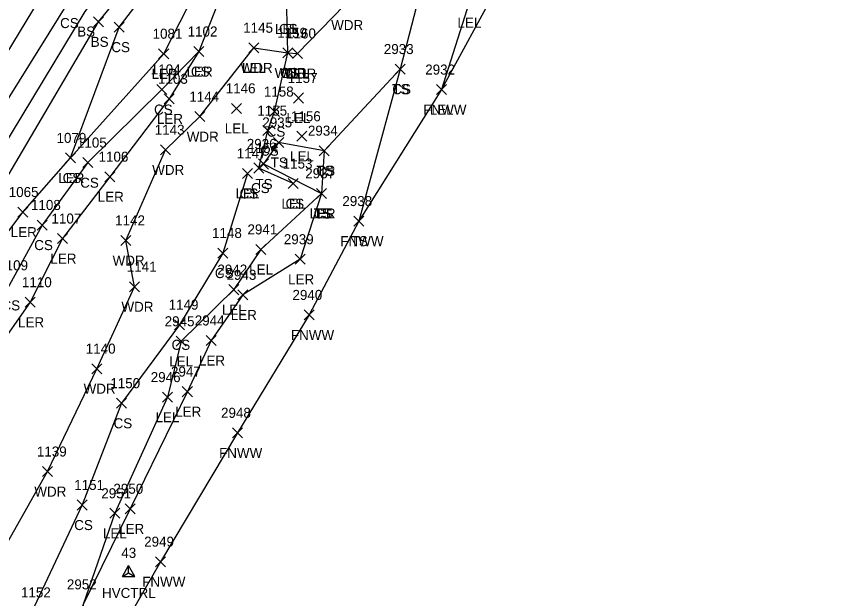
# Model space of a CAD drawing. Extents: x 1483143 to 1488182, y 802902 to 807581.
# Drawn here: x 1487188.6 to 1487354.4, y 804993.1 to 805109.1 of the extents above; entities that cross this region are included whole.
import ezdxf

# ---------------------------------------------------------------- set-up
doc = ezdxf.new("R2010")
doc.units = 0
for name, color, linetype in [('C_A', 7, 'Continuous'), ('C_I', 7, 'Continuous'), ('CPSM', 7, 'Continuous'), ('L_A', 7, 'Continuous'), ('L_I', 7, 'Continuous'), ('L_TIC', 7, 'Continuous'), ('LARO', 7, 'Continuous'), ('LAWA', 7, 'Continuous'), ('LELB', 7, 'Continuous'), ('LFNC', 7, 'Continuous')]:
    doc.layers.add(name, color=color, linetype=linetype)

msp = doc.modelspace()

# ---------------------------------------------------------------- linework, layer by layer
at = {"layer": 'CPSM'}
for p, q in [((1487209.65, 804997.5), (1487210.9, 804999.66)), ((1487212.15, 804997.5), (1487210.9, 804999.66)), ((1487210.9, 804998.22), (1487210.9, 804999.66)), ((1487209.65, 804997.5), (1487210.9, 804998.22)), ((1487209.65, 804997.5), (1487212.15, 804997.5)), ((1487210.9, 804998.22), (1487210.9, 804998.22)), ((1487210.9, 804998.22), (1487212.15, 804997.5))]:
    msp.add_line(p, q, dxfattribs=at)
at = {"layer": 'L_TIC'}
for points in [[(1487203.9, 805107.12), (1487205.9, 805109.12)], [(1487205.9, 805107.12), (1487203.9, 805109.12)], [(1487208.02, 805106.06), (1487210.02, 805108.06)], [(1487210.02, 805106.06), (1487208.02, 805108.06)], [(1487223.88, 805101.18), (1487225.88, 805103.18)], [(1487225.88, 805101.18), (1487223.88, 805103.18)], [(1487223.88, 805101.18), (1487225.88, 805103.18)], [(1487225.88, 805101.18), (1487223.88, 805103.18)], [(1487234.87, 805101.93), (1487236.87, 805103.93)], [(1487236.87, 805101.93), (1487234.87, 805103.93)], [(1487234.87, 805101.93), (1487236.87, 805103.93)], [(1487236.87, 805101.93), (1487234.87, 805103.93)], [(1487216.89, 805100.74), (1487218.89, 805102.74)], [(1487218.89, 805100.74), (1487216.89, 805102.74)], [(1487241.66, 805100.92), (1487243.66, 805102.92)], [(1487243.66, 805100.92), (1487241.66, 805102.92)], [(1487241.66, 805100.92), (1487243.66, 805102.92)], [(1487243.66, 805100.92), (1487241.66, 805102.92)], [(1487243.56, 805100.79), (1487245.56, 805102.79)], [(1487245.56, 805100.79), (1487243.56, 805102.79)], [(1487243.56, 805100.79), (1487245.56, 805102.79)], [(1487245.56, 805100.79), (1487243.56, 805102.79)], [(1487264.05, 805097.68), (1487266.05, 805099.68)], [(1487266.05, 805097.68), (1487264.05, 805099.68)], [(1487264.05, 805097.68), (1487266.05, 805099.68)], [(1487266.05, 805097.68), (1487264.05, 805099.68)], [(1487216.52, 805093.61), (1487218.52, 805095.61)], [(1487218.52, 805093.61), (1487216.52, 805095.61)], [(1487272.31, 805093.59), (1487274.31, 805095.59)], [(1487274.31, 805093.59), (1487272.31, 805095.59)], [(1487272.31, 805093.59), (1487274.31, 805095.59)], [(1487274.31, 805093.59), (1487272.31, 805095.59)], [(1487217.96, 805091.75), (1487219.96, 805093.75)], [(1487219.96, 805091.75), (1487217.96, 805093.75)], [(1487243.75, 805091.92), (1487245.75, 805093.92)], [(1487245.75, 805091.92), (1487243.75, 805093.92)], [(1487231.44, 805089.85), (1487233.44, 805091.85)], [(1487233.44, 805089.85), (1487231.44, 805091.85)], [(1487224.12, 805088.2), (1487226.12, 805090.2)], [(1487226.12, 805088.2), (1487224.12, 805090.2)], [(1487238.99, 805089.2), (1487240.99, 805091.2)], [(1487240.99, 805089.2), (1487238.99, 805091.2)], [(1487237.69, 805085.41), (1487239.69, 805087.41)], [(1487239.69, 805085.41), (1487237.69, 805087.41)], [(1487239.82, 805083.06), (1487241.82, 805085.06)], [(1487241.82, 805083.06), (1487239.82, 805085.06)], [(1487244.45, 805084.28), (1487246.45, 805086.28)], [(1487246.45, 805084.28), (1487244.45, 805086.28)], [(1487217.24, 805081.58), (1487219.24, 805083.58)], [(1487219.24, 805081.58), (1487217.24, 805083.58)], [(1487248.91, 805081.41), (1487250.91, 805083.41)], [(1487250.91, 805081.41), (1487248.91, 805083.41)], [(1487248.91, 805081.41), (1487250.91, 805083.41)], [(1487250.91, 805081.41), (1487248.91, 805083.41)], [(1487198.3, 805079.96), (1487200.3, 805081.96)], [(1487200.3, 805079.96), (1487198.3, 805081.96)], [(1487198.3, 805079.96), (1487200.3, 805081.96)], [(1487200.3, 805079.96), (1487198.3, 805081.96)], [(1487201.79, 805079.03), (1487203.79, 805081.03)], [(1487203.79, 805079.03), (1487201.79, 805081.03)], [(1487235.87, 805077.96), (1487237.87, 805079.96)], [(1487237.87, 805077.96), (1487235.87, 805079.96)], [(1487236.78, 805078.76), (1487238.78, 805080.76)], [(1487238.78, 805078.76), (1487236.78, 805080.76)], [(1487206.16, 805076.22), (1487208.16, 805078.22)], [(1487208.16, 805076.22), (1487206.16, 805078.22)], [(1487233.59, 805076.88), (1487235.59, 805078.88)], [(1487235.59, 805076.88), (1487233.59, 805078.88)], [(1487233.59, 805076.88), (1487235.59, 805078.88)], [(1487235.59, 805076.88), (1487233.59, 805078.88)], [(1487242.74, 805074.84), (1487244.74, 805076.84)], [(1487244.74, 805074.84), (1487242.74, 805076.84)], [(1487242.74, 805074.84), (1487244.74, 805076.84)], [(1487244.74, 805074.84), (1487242.74, 805076.84)], [(1487248.38, 805072.9), (1487250.38, 805074.9)], [(1487250.38, 805072.9), (1487248.38, 805074.9)], [(1487248.38, 805072.9), (1487250.38, 805074.9)], [(1487250.38, 805072.9), (1487248.38, 805074.9)], [(1487248.38, 805072.9), (1487250.38, 805074.9)], [(1487250.38, 805072.9), (1487248.38, 805074.9)], [(1487248.38, 805072.9), (1487250.38, 805074.9)], [(1487250.38, 805072.9), (1487248.38, 805074.9)], [(1487188.8, 805069.17), (1487190.8, 805071.17)], [(1487190.8, 805069.17), (1487188.8, 805071.17)], [(1487192.63, 805066.59), (1487194.63, 805068.59)], [(1487194.63, 805066.59), (1487192.63, 805068.59)], [(1487255.78, 805067.37), (1487257.78, 805069.37)], [(1487257.78, 805067.37), (1487255.78, 805069.37)], [(1487255.78, 805067.37), (1487257.78, 805069.37)], [(1487257.78, 805067.37), (1487255.78, 805069.37)], [(1487196.72, 805063.88), (1487198.72, 805065.88)], [(1487198.72, 805063.88), (1487196.72, 805065.88)], [(1487209.34, 805063.51), (1487211.34, 805065.51)], [(1487211.34, 805063.51), (1487209.34, 805065.51)], [(1487236.29, 805061.72), (1487238.29, 805063.72)], [(1487238.29, 805061.72), (1487236.29, 805063.72)], [(1487228.66, 805061), (1487230.66, 805063)], [(1487230.66, 805061), (1487228.66, 805063)], [(1487244.12, 805059.76), (1487246.12, 805061.76)], [(1487246.12, 805059.76), (1487244.12, 805061.76)], [(1487211.1, 805054.28), (1487213.1, 805056.28)], [(1487213.1, 805054.28), (1487211.1, 805056.28)], [(1487230.86, 805053.7), (1487232.86, 805055.7)], [(1487232.86, 805053.7), (1487230.86, 805055.7)], [(1487232.68, 805052.66), (1487234.68, 805054.66)], [(1487234.68, 805052.66), (1487232.68, 805054.66)], [(1487190.27, 805051.19), (1487192.27, 805053.19)], [(1487192.27, 805051.19), (1487190.27, 805053.19)], [(1487245.92, 805048.65), (1487247.92, 805050.65)], [(1487247.92, 805048.65), (1487245.92, 805050.65)], [(1487220.02, 805046.7), (1487222.02, 805048.7)], [(1487222.02, 805046.7), (1487220.02, 805048.7)], [(1487220.35, 805043.4), (1487222.35, 805045.4)], [(1487222.35, 805043.4), (1487220.35, 805045.4)], [(1487226.35, 805043.56), (1487228.35, 805045.56)], [(1487228.35, 805043.56), (1487226.35, 805045.56)], [(1487203.56, 805037.94), (1487205.56, 805039.94)], [(1487205.56, 805037.94), (1487203.56, 805039.94)], [(1487221.61, 805033.36), (1487223.61, 805035.36)], [(1487223.61, 805033.36), (1487221.61, 805035.36)], [(1487217.63, 805032.26), (1487219.63, 805034.26)], [(1487219.63, 805032.26), (1487217.63, 805034.26)], [(1487208.46, 805031.05), (1487210.46, 805033.05)], [(1487210.46, 805031.05), (1487208.46, 805033.05)], [(1487231.59, 805025.14), (1487233.59, 805027.14)], [(1487233.59, 805025.14), (1487231.59, 805027.14)], [(1487193.73, 805017.42), (1487195.73, 805019.42)], [(1487195.73, 805017.42), (1487193.73, 805019.42)], [(1487200.61, 805010.76), (1487202.61, 805012.76)], [(1487202.61, 805010.76), (1487200.61, 805012.76)], [(1487210.22, 805010), (1487212.22, 805012)], [(1487212.22, 805010), (1487210.22, 805012)], [(1487207.14, 805009.1), (1487209.14, 805011.1)], [(1487209.14, 805009.1), (1487207.14, 805011.1)], [(1487216.26, 804999.45), (1487218.26, 805001.45)], [(1487218.26, 804999.45), (1487216.26, 805001.45)]]:
    msp.add_lwpolyline(points, dxfattribs=at)
at = {"layer": 'LARO'}
for points in [[(1487124.31, 804973.13), (1487145.49, 805006.81), (1487169.77, 805044.38), (1487180.59, 805057.87), (1487189.8, 805070.17), (1487199.3, 805080.96), (1487217.89, 805101.74), (1487229.45, 805124.32), (1487246.83, 805150.76), (1487254.41, 805169.19), (1487269.28, 805204.96), (1487282.34, 805212.7), (1487284.63, 805226.5), (1487290.62, 805235.83), (1487297.31, 805243.76), (1487306.73, 805267.09), (1487309.81, 805276.71), (1487327.69, 805305.4), (1487333.49, 805320.05), (1487351.27, 805341.81), (1487376.58, 805390.13), (1487400.9, 805431.24), (1487423.77, 805476.17), (1487448.72, 805522.61)], [(1487294.36, 805131.51), (1487282.19, 805124.75), (1487278.84, 805111.94), (1487273.31, 805094.59)], [(1487224.88, 805102.18), (1487218.96, 805092.75), (1487207.16, 805077.22), (1487197.72, 805064.88), (1487191.27, 805052.19), (1487172.27, 805025.16), (1487162.87, 805006.15), (1487154.72, 804982.09), (1487145.82, 804977.85), (1487136.39, 804963.75), (1487123.38, 804946.04), (1487114.55, 804933.59), (1487107.15, 804926.23), (1487097.47, 804917.18), (1487108.5, 804913.17)], [(1487249.38, 805073.9), (1487237.29, 805062.72), (1487231.86, 805054.7), (1487221.35, 805044.4), (1487218.63, 805033.26), (1487208.14, 805010.1), (1487201.85, 804991.93), (1487196.68, 804979.98), (1487199.24, 804969.27)], [(1487249.38, 805073.9), (1487245.12, 805060.76), (1487233.68, 805053.66), (1487227.35, 805044.56), (1487222.61, 805034.36), (1487211.22, 805011), (1487201.85, 804991.93), (1487203.24, 804976.05)]]:
    msp.add_lwpolyline(points, dxfattribs=at)
at = {"layer": 'LAWA'}
msp.add_lwpolyline([(1487164.31, 804973.06), (1487181.36, 804994.82), (1487194.73, 805018.42), (1487204.56, 805038.94), (1487212.1, 805055.28), (1487210.34, 805064.51), (1487218.24, 805082.58), (1487225.12, 805089.2), (1487235.87, 805102.93), (1487242.66, 805101.92), (1487244.56, 805101.79), (1487253.92, 805111.46), (1487254.69, 805139.81), (1487264.81, 805134.72), (1487277.92, 805155.83), (1487279.64, 805173.04), (1487288.55, 805192.53), (1487294.52, 805206.51)], dxfattribs=at)
at = {"layer": 'LELB'}
for points in [[(1487199.3, 805080.96), (1487209.02, 805107.06), (1487224.53, 805127.21), (1487240.95, 805152.24), (1487249.95, 805171.94), (1487269.65, 805210.5), (1487285.86, 805237.33), (1487303.36, 805267.84), (1487322.25, 805302.17), (1487347.45, 805347.07), (1487376.58, 805390.13), (1487398.58, 805433.78), (1487419.88, 805479.75), (1487445.41, 805524.09), (1487470.45, 805569.86), (1487486.06, 805603.16), (1487492.1, 805615.56), (1487500.68, 805632.42), (1487507.33, 805640.17), (1487520.3, 805671.34), (1487528.77, 805686.31), (1487539.17, 805698.49)], [(1487108.71, 804980.78), (1487132.66, 805016.32), (1487156.92, 805053.98), (1487173.31, 805079.98), (1487194.46, 805114.79), (1487207.05, 805135.95), (1487220.86, 805159.73), (1487233.38, 805181.3), (1487254.33, 805216.27), (1487271.44, 805245.69), (1487289.79, 805275.85), (1487308.89, 805309.94), (1487335.6, 805356.15), (1487359.27, 805398.59), (1487383.94, 805443.57), (1487406.66, 805485.41), (1487431.45, 805531.24)], [(1487141.45, 805012.57), (1487160.97, 805051.58), (1487177.59, 805077.87), (1487198.8, 805111.86), (1487211.59, 805133.5), (1487225.91, 805156.73), (1487238.62, 805176.26), (1487258.28, 805214.16), (1487275.11, 805243.36), (1487293.13, 805273.9), (1487313.26, 805307.35), (1487339.04, 805353.08), (1487362.83, 805397.01), (1487388.55, 805442.86), (1487410.04, 805483.24), (1487436.07, 805529.53)], [(1487115.55, 804977.3), (1487141.45, 805012.57), (1487163.51, 805049.72), (1487181.31, 805075.62), (1487202.21, 805110.17), (1487217.83, 805130.45), (1487232, 805156.36), (1487242.54, 805175.79), (1487260.94, 805211.88), (1487278.65, 805241.13), (1487296.94, 805270.92), (1487316.03, 805304.83), (1487341.87, 805350.7), (1487367.6, 805395.34), (1487392.63, 805437.94), (1487413.83, 805481.53), (1487440.22, 805526.89)], [(1487119.27, 804975.75), (1487145.32, 805010.11), (1487166.09, 805047.54), (1487184.56, 805073.64), (1487204.9, 805108.12), (1487221.47, 805128.3), (1487235.08, 805155.22), (1487247.48, 805170.55), (1487262.97, 805210.14), (1487282.96, 805240.11), (1487299.52, 805269.42), (1487319.05, 805303.47), (1487344.42, 805349.03), (1487372.12, 805390.86), (1487397.58, 805436.46), (1487417, 805480.8), (1487442.28, 805525.8)], [(1487243.74, 805075.84), (1487236.87, 805078.96), (1487238.69, 805086.41), (1487239.99, 805090.2), (1487242.66, 805101.92), (1487242.45, 805110.69), (1487247.2, 805124.73), (1487252.07, 805141.93), (1487257.35, 805153.28), (1487261.02, 805166.68), (1487265.7, 805175.24), (1487270.25, 805187.46), (1487269.03, 805191.93), (1487273.39, 805203.42), (1487279.08, 805203.72)], [(1487246.83, 805150.76), (1487242.89, 805139.86), (1487233.12, 805123.13), (1487224.88, 805102.18), (1487217.52, 805094.61), (1487202.79, 805080.03), (1487193.63, 805067.59), (1487187.1, 805055.56), (1487168.64, 805033.48), (1487158.81, 805020.55), (1487157.67, 805011.55), (1487148.3, 805000.05), (1487147.3, 804990.5), (1487140.47, 804987.56), (1487138.01, 804979.27), (1487134.54, 804971.88), (1487127.64, 804963.81), (1487118.59, 804952.09), (1487110, 804937.1), (1487101.9, 804929.94), (1487094.26, 804919.39), (1487097.47, 804917.18)], [(1487282.19, 805124.75), (1487270.03, 805117.96), (1487265.05, 805098.68), (1487256.78, 805068.37)], [(1487265.05, 805098.68), (1487249.91, 805082.41), (1487249.38, 805073.9)], [(1487249.91, 805082.41), (1487240.82, 805084.06), (1487237.78, 805079.76), (1487249.38, 805073.9)], [(1487234.59, 805077.88), (1487229.66, 805062), (1487221.02, 805047.7), (1487209.46, 805032.05), (1487201.61, 805011.76), (1487191.55, 804990.32)]]:
    msp.add_lwpolyline(points, dxfattribs=at)
at = {"layer": 'LFNC'}
msp.add_lwpolyline([(1487486.09, 805303.62), (1487464.01, 805287.37), (1487426.01, 805259.99), (1487401.42, 805242.52), (1487400.19, 805241.82), (1487381.81, 805228.11), (1487374.75, 805223.04), (1487372.52, 805220.64), (1487362.23, 805213.48), (1487358.33, 805209.86), (1487353.9, 805206.31), (1487340.39, 805197.17), (1487324.4, 805185.57), (1487312.71, 805164.9), (1487301.18, 805144.21), (1487298.04, 805137.83), (1487294.36, 805131.51), (1487284.56, 805115.26), (1487273.31, 805094.59), (1487256.78, 805068.37), (1487246.92, 805049.65), (1487232.59, 805026.14), (1487217.26, 805000.45), (1487203.24, 804976.05)], dxfattribs=at)

# ---------------------------------------------------------------- texts
at = {"layer": 'C_A'}
msp.add_text('HVCTRL', height=2, dxfattribs=at).set_placement((1487205.6, 804993.22))
at = {"layer": 'C_I'}
msp.add_text('43', height=2, dxfattribs=at).set_placement((1487209.44, 805001.22))
at = {"layer": 'L_A'}
for s, p in [('CS', (1487197.24, 805106.86)), ('WDR', (1487251.29, 805106.46)), ('LEL', (1487276.48, 805106.94)), ('BS', (1487200.65, 805105.17)), ('LEL', (1487240.09, 805105.69)), ('CS', (1487240.89, 805105.69)), ('BS', (1487203.34, 805103.12)), ('CS', (1487207.46, 805102.06)), ('WDR', (1487233.23, 805097.93)), ('LEL', (1487233.51, 805097.93)), ('LER', (1487215.47, 805096.74)), ('LER', (1487222.46, 805097.18)), ('CS', (1487223.32, 805097.18)), ('WDR', (1487240.02, 805096.92)), ('CS', (1487241.1, 805096.92)), ('WDR', (1487241.92, 805096.79)), ('LEL', (1487242.2, 805096.79)), ('TS', (1487263.46, 805093.68)), ('CS', (1487263.49, 805093.68)), ('CS', (1487215.97, 805089.61)), ('FNWW', (1487269.66, 805089.59)), ('LEL', (1487270.95, 805089.59)), ('LER', (1487216.54, 805087.75)), ('LEL', (1487242.38, 805087.92)), ('LEL', (1487230.08, 805085.85)), ('CS', (1487238.43, 805085.2)), ('WDR', (1487222.49, 805084.2)), ('CS', (1487237.13, 805081.41)), ('LEL', (1487243.09, 805080.28)), ('TS', (1487239.23, 805079.06)), ('WDR', (1487215.6, 805077.58)), ('TS', (1487248.32, 805077.41)), ('CS', (1487248.35, 805077.41)), ('LER', (1487196.88, 805075.96)), ('CS', (1487197.74, 805075.96)), ('CS', (1487201.24, 805075.03)), ('TS', (1487236.19, 805074.76)), ('LEL', (1487232.23, 805072.88)), ('CS', (1487233.03, 805072.88)), ('CS', (1487235.31, 805073.96)), ('LER', (1487204.74, 805072.22)), ('LEL', (1487241.38, 805070.84)), ('CS', (1487242.19, 805070.84)), ('LER', (1487246.96, 805068.9)), ('LEL', (1487247.01, 805068.9)), ('TS', (1487247.79, 805068.9)), ('CS', (1487247.82, 805068.9)), ('LER', (1487187.39, 805065.17)), ('FNWW', (1487253.13, 805063.37)), ('TS', (1487255.19, 805063.37)), ('CS', (1487192.08, 805062.59)), ('LER', (1487195.3, 805059.88)), ('WDR', (1487207.7, 805059.51)), ('CS', (1487228.1, 805057)), ('LEL', (1487234.93, 805057.72)), ('LER', (1487242.7, 805055.76)), ('CS', (1487185.55, 805050.56)), ('WDR', (1487209.47, 805050.28)), ('LEL', (1487229.5, 805049.7)), ('LER', (1487231.27, 805048.66)), ('LER', (1487188.85, 805047.19)), ('FNWW', (1487243.27, 805044.65)), ('CS', (1487219.46, 805042.7)), ('LEL', (1487218.99, 805039.4)), ('LER', (1487224.93, 805039.56)), ('WDR', (1487201.93, 805033.94)), ('LEL', (1487216.26, 805028.26)), ('LER', (1487220.19, 805029.36)), ('CS', (1487207.9, 805027.05)), ('FNWW', (1487228.94, 805021.14)), ('WDR', (1487192.1, 805013.42)), ('CS', (1487200.05, 805006.76)), ('LEL', (1487205.78, 805005.1)), ('LER', (1487208.8, 805006)), ('FNWW', (1487213.61, 804995.45))]:
    msp.add_text(s, height=2, dxfattribs=at).set_placement(p)
at = {"layer": 'L_I'}
for s, p in [('1081', (1487215.68, 805104.74)), ('1102', (1487222.67, 805105.18)), ('1102', (1487222.67, 805105.18)), ('1145', (1487233.74, 805105.93)), ('1145', (1487233.74, 805105.93)), ('1159', (1487240.52, 805104.92)), ('1159', (1487240.52, 805104.92)), ('1160', (1487242.3, 805104.79)), ('1160', (1487242.3, 805104.79)), ('2933', (1487261.79, 805101.68)), ('2933', (1487261.79, 805101.68)), ('1104', (1487215.32, 805097.61)), ('2932', (1487270.05, 805097.59)), ('2932', (1487270.05, 805097.59)), ('1103', (1487216.76, 805095.75)), ('1157', (1487242.62, 805095.92)), ('1146', (1487230.26, 805093.85)), ('1158', (1487237.87, 805093.2)), ('1144', (1487223, 805092.2)), ('1155', (1487236.56, 805089.41)), ('1156', (1487243.27, 805088.28)), ('2935', (1487237.56, 805087.06)), ('1143', (1487216.11, 805085.58)), ('2934', (1487246.65, 805085.41)), ('2934', (1487246.65, 805085.41)), ('1079', (1487196.52, 805083.96)), ('1079', (1487196.52, 805083.96)), ('1105', (1487200.59, 805083.03)), ('2936', (1487234.46, 805082.76)), ('1154', (1487234.75, 805081.96)), ('1106', (1487204.9, 805080.22)), ('1147', (1487232.46, 805080.88)), ('1147', (1487232.46, 805080.88)), ('1153', (1487241.62, 805078.84)), ('1153', (1487241.62, 805078.84)), ('2937', (1487246.12, 805076.9)), ('2937', (1487246.12, 805076.9)), ('2937', (1487246.12, 805076.9)), ('2937', (1487246.12, 805076.9)), ('1065', (1487186.99, 805073.17)), ('2938', (1487253.52, 805071.37)), ('2938', (1487253.52, 805071.37)), ('1108', (1487191.43, 805070.59)), ('1107', (1487195.51, 805067.88)), ('1142', (1487208.21, 805067.51)), ('1148', (1487227.53, 805065)), ('2941', (1487234.6, 805065.72)), ('2939', (1487241.85, 805063.76)), ('1109', (1487184.89, 805058.56)), ('1141', (1487210.54, 805058.28)), ('2942', (1487228.6, 805057.7)), ('2943', (1487230.42, 805056.66)), ('1110', (1487189.62, 805055.19)), ('2940', (1487243.57, 805052.65)), ('1149', (1487218.88, 805050.7)), ('2945', (1487218.09, 805047.4)), ('2944', (1487224.09, 805047.56)), ('1140', (1487202.35, 805041.94)), ('2947', (1487219.35, 805037.36)), ('1150', (1487207.25, 805035.05)), ('2946', (1487215.31, 805036.26)), ('2948', (1487229.33, 805029.14)), ('1139', (1487192.6, 805021.42)), ('1151', (1487200.05, 805014.76)), ('2951', (1487205.45, 805013.1)), ('2950', (1487207.87, 805014)), ('2949', (1487214, 805003.45)), ('2952', (1487198.59, 804994.93)), ('2952', (1487198.59, 804994.93)), ('2952', (1487198.59, 804994.93)), ('1152', (1487189.43, 804993.32))]:
    msp.add_text(s, height=2, dxfattribs=at).set_placement(p)

doc.saveas('drawing.dxf')
